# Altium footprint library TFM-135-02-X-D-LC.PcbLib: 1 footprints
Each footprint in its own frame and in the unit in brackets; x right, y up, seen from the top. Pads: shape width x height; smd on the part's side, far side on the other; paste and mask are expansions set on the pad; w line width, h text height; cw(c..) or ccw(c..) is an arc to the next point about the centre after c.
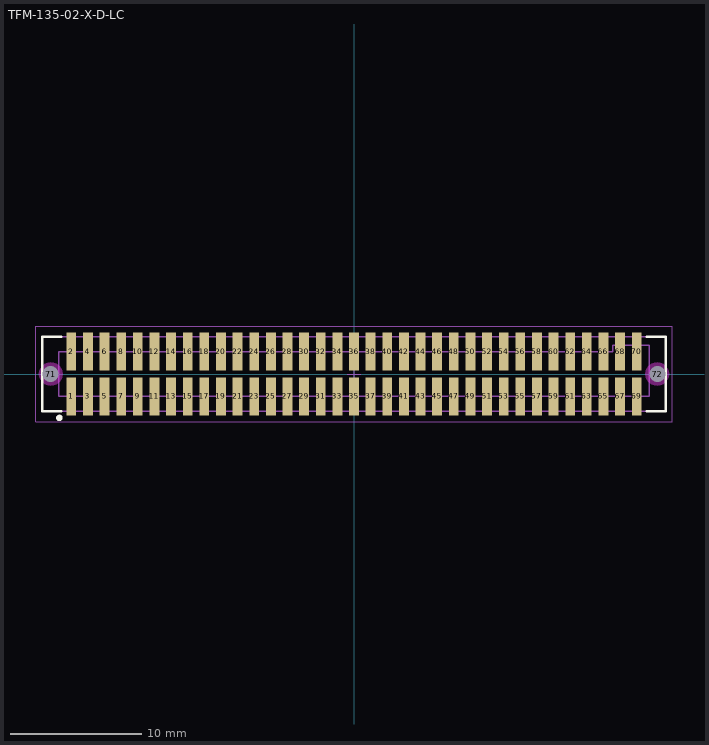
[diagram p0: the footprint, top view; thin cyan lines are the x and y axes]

## TFM-135-02-X-D-LC [mm] "1.27mm pitch, 70 pin, terminal strip; w/locking clips, SMT"
height 5.72
pads (72):
  rect 0.75x2.9 smd mask+0: 1(-21.59,-1.714) 2(-21.59,1.714) 3(-20.32,-1.714) 4(-20.32,1.714) 5(-19.05,-1.714) 6(-19.05,1.714) 7(-17.78,-1.714) 8(-17.78,1.714) 9(-16.51,-1.714) 10(-16.51,1.714) 11(-15.24,-1.714) 12(-15.24,1.714) 13(-13.97,-1.714) 14(-13.97,1.714) 15(-12.7,-1.714) 16(-12.7,1.714) 17(-11.43,-1.714) 18(-11.43,1.714) 19(-10.16,-1.714) 20(-10.16,1.714) 21(-8.89,-1.714) 22(-8.89,1.714) 23(-7.62,-1.714) 24(-7.62,1.714) 25(-6.35,-1.714) 26(-6.35,1.714) 27(-5.08,-1.714) 28(-5.08,1.714) 29(-3.81,-1.714) 30(-3.81,1.714) 31(-2.54,-1.714) 32(-2.54,1.714) 33(-1.27,-1.714) 34(-1.27,1.714) 35(0,-1.714) 36(0,1.714) 37(1.27,-1.714) 38(1.27,1.714) 39(2.54,-1.714) 40(2.54,1.714) 41(3.81,-1.714) 42(3.81,1.714) 43(5.08,-1.714) 44(5.08,1.714) 45(6.35,-1.714) 46(6.35,1.714) 47(7.62,-1.714) 48(7.62,1.714) 49(8.89,-1.714) 50(8.89,1.714) 51(10.16,-1.714) 52(10.16,1.714) 53(11.43,-1.714) 54(11.43,1.714) 55(12.7,-1.714) 56(12.7,1.714) 57(13.97,-1.714) 58(13.97,1.714) 59(15.24,-1.714) 60(15.24,1.714) 61(16.51,-1.714) 62(16.51,1.714) 63(17.78,-1.714) 64(17.78,1.714) 65(19.05,-1.714) 66(19.05,1.714) 67(20.32,-1.714) 68(20.32,1.714) 69(21.59,-1.714) 70(21.59,1.714)
  round 1 hole 1.2 unplated mask+0: 71(-23.177,0) 72(23.177,0)
Top Overlay:
  circle w0.25: c-22.5,-3.35 r0.125
  lines w0.2: -22.35,-2.85 -23.8,-2.85 -23.8,2.85 -22.35,2.85 ; 22.35,-2.85 23.8,-2.85 23.8,2.85 22.35,2.85
Keep-Out Layer:
  pour cut-out: 24.06,0 24.03,0.235 23.939,0.454 23.795,0.642 23.607,0.786 23.388,0.877 23.153,0.908 22.918,0.877 22.699,0.786 22.511,0.642 22.367,0.454 22.276,0.235 22.245,0 22.276,-0.235 22.367,-0.454 22.511,-0.642 22.699,-0.786 22.918,-0.877 23.153,-0.908 23.388,-0.877 23.607,-0.786 23.795,-0.642 23.939,-0.454 24.03,-0.235
  pour cut-out: -22.245,0 -22.276,0.235 -22.367,0.454 -22.511,0.642 -22.699,0.786 -22.918,0.877 -23.153,0.908 -23.388,0.877 -23.607,0.786 -23.795,0.642 -23.939,0.454 -24.03,0.235 -24.06,0 -24.03,-0.235 -23.939,-0.454 -23.795,-0.642 -23.607,-0.786 -23.388,-0.877 -23.153,-0.908 -22.918,-0.877 -22.699,-0.786 -22.511,-0.642 -22.367,-0.454 -22.276,-0.235
Mechanical 12:
  lines w0.001: -23.8,-2.85 -23.8,2.85 23.8,2.85 23.8,-2.85 -23.8,-2.85 ; -22.55,-1.7 -22.55,1.7 19.75,1.7 19.75,2.2 22.55,2.2 22.55,-1.7 -22.55,-1.7
Mechanical 13:
  circle w0.1: c-22.506,-3.355 r0.127
  lines w0.1: -23.8,-2.85 -23.8,2.85 23.8,2.85 23.8,-2.85 -23.8,-2.85 ; -22.55,-1.7 -22.55,1.7 19.75,1.7 19.75,2.2 22.55,2.2 22.55,-1.7 -22.55,-1.7
  text ".Designator" at 0,-0.127 h1.52
Mechanical 15:
  lines w0.05: -0.5,0 0.5,0 ; 0,-0.5 0,0.5 ; -24.3,-3.65 -24.3,3.65 24.3,3.65 24.3,-3.65 -24.3,-3.65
